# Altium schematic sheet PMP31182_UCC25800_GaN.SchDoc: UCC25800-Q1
size A2; Date: Not shown in title block; ApprovedBy: Not shown in title block; CheckedBy: Not shown in title block; Author: Not shown in title block; CompanyName: Not shown in title block; Engineer: Not shown in title block; Organization: Not shown in title block; Address1: Not shown in title block; Address2: Not shown in title block; Address3: Not shown in title block; Address4: Not shown in title block; DocumentNumber: 2; Revision: Use project parameter SCH_Rev; SheetNumber: 2; SheetTotal: 3; PageSetup: Record=PageOptions¦CenterHorizontal=True¦CenterVertical=True¦PrintScale=1.00¦XCorrection=1.00¦YCorrection=1.00¦PrintKind=0¦BorderSize=5000000¦LeftOffset=0¦BottomOffset=0¦Orientation=2¦PaperLength=1000¦PaperWidth=1000¦Scale=100¦PaperSource=15¦PrintQuality=600¦MediaType=1¦DitherType=10¦PaperKind=Letter¦PrintScaleMode=1
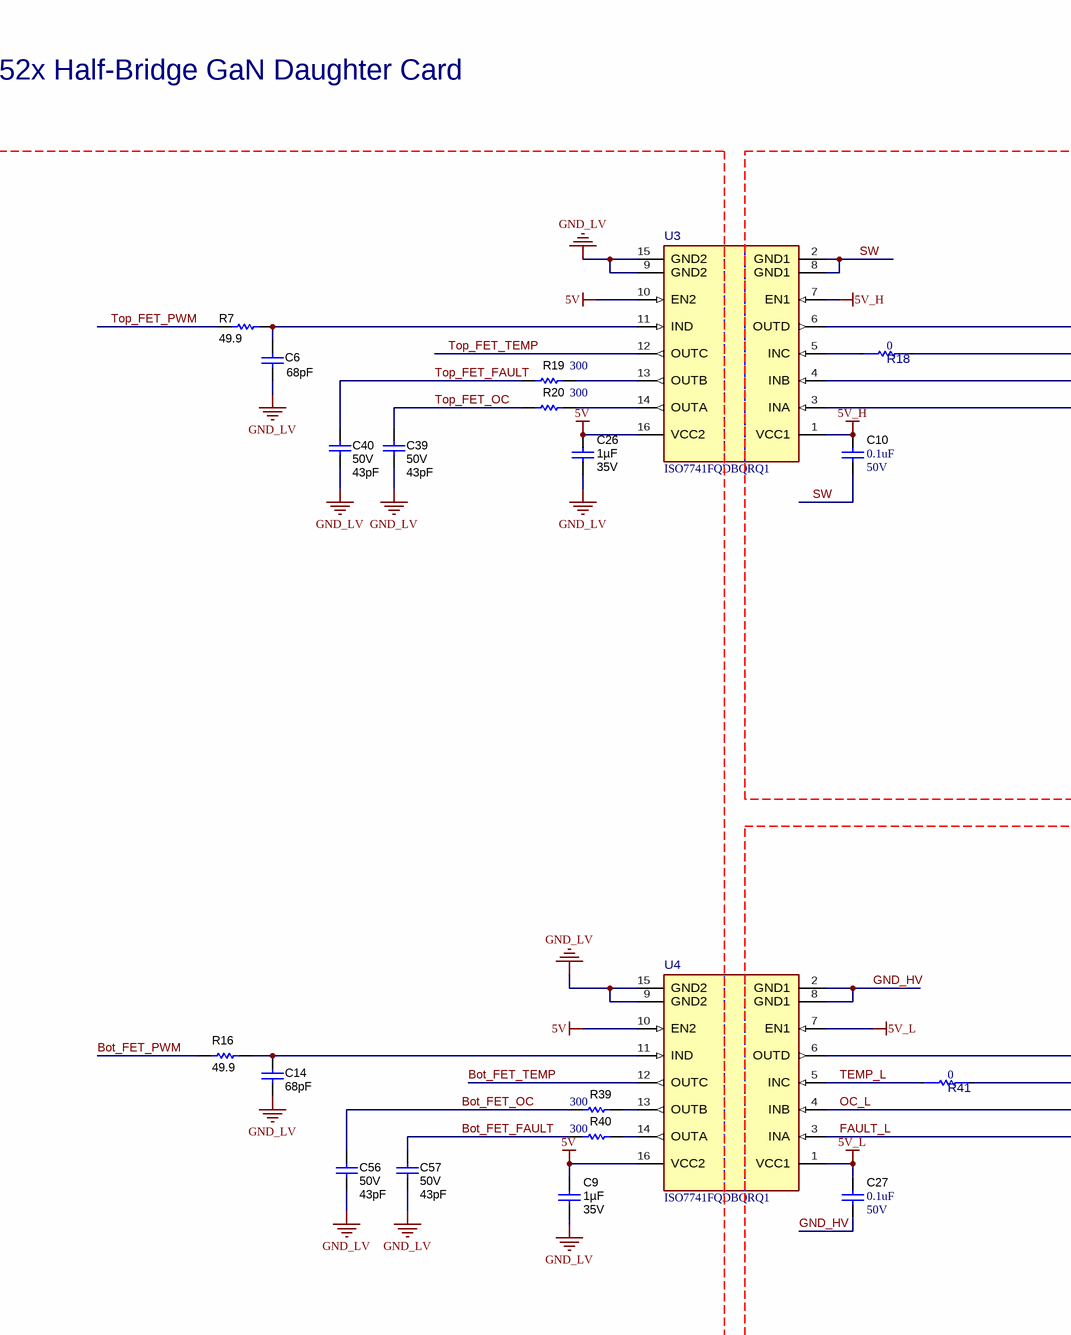
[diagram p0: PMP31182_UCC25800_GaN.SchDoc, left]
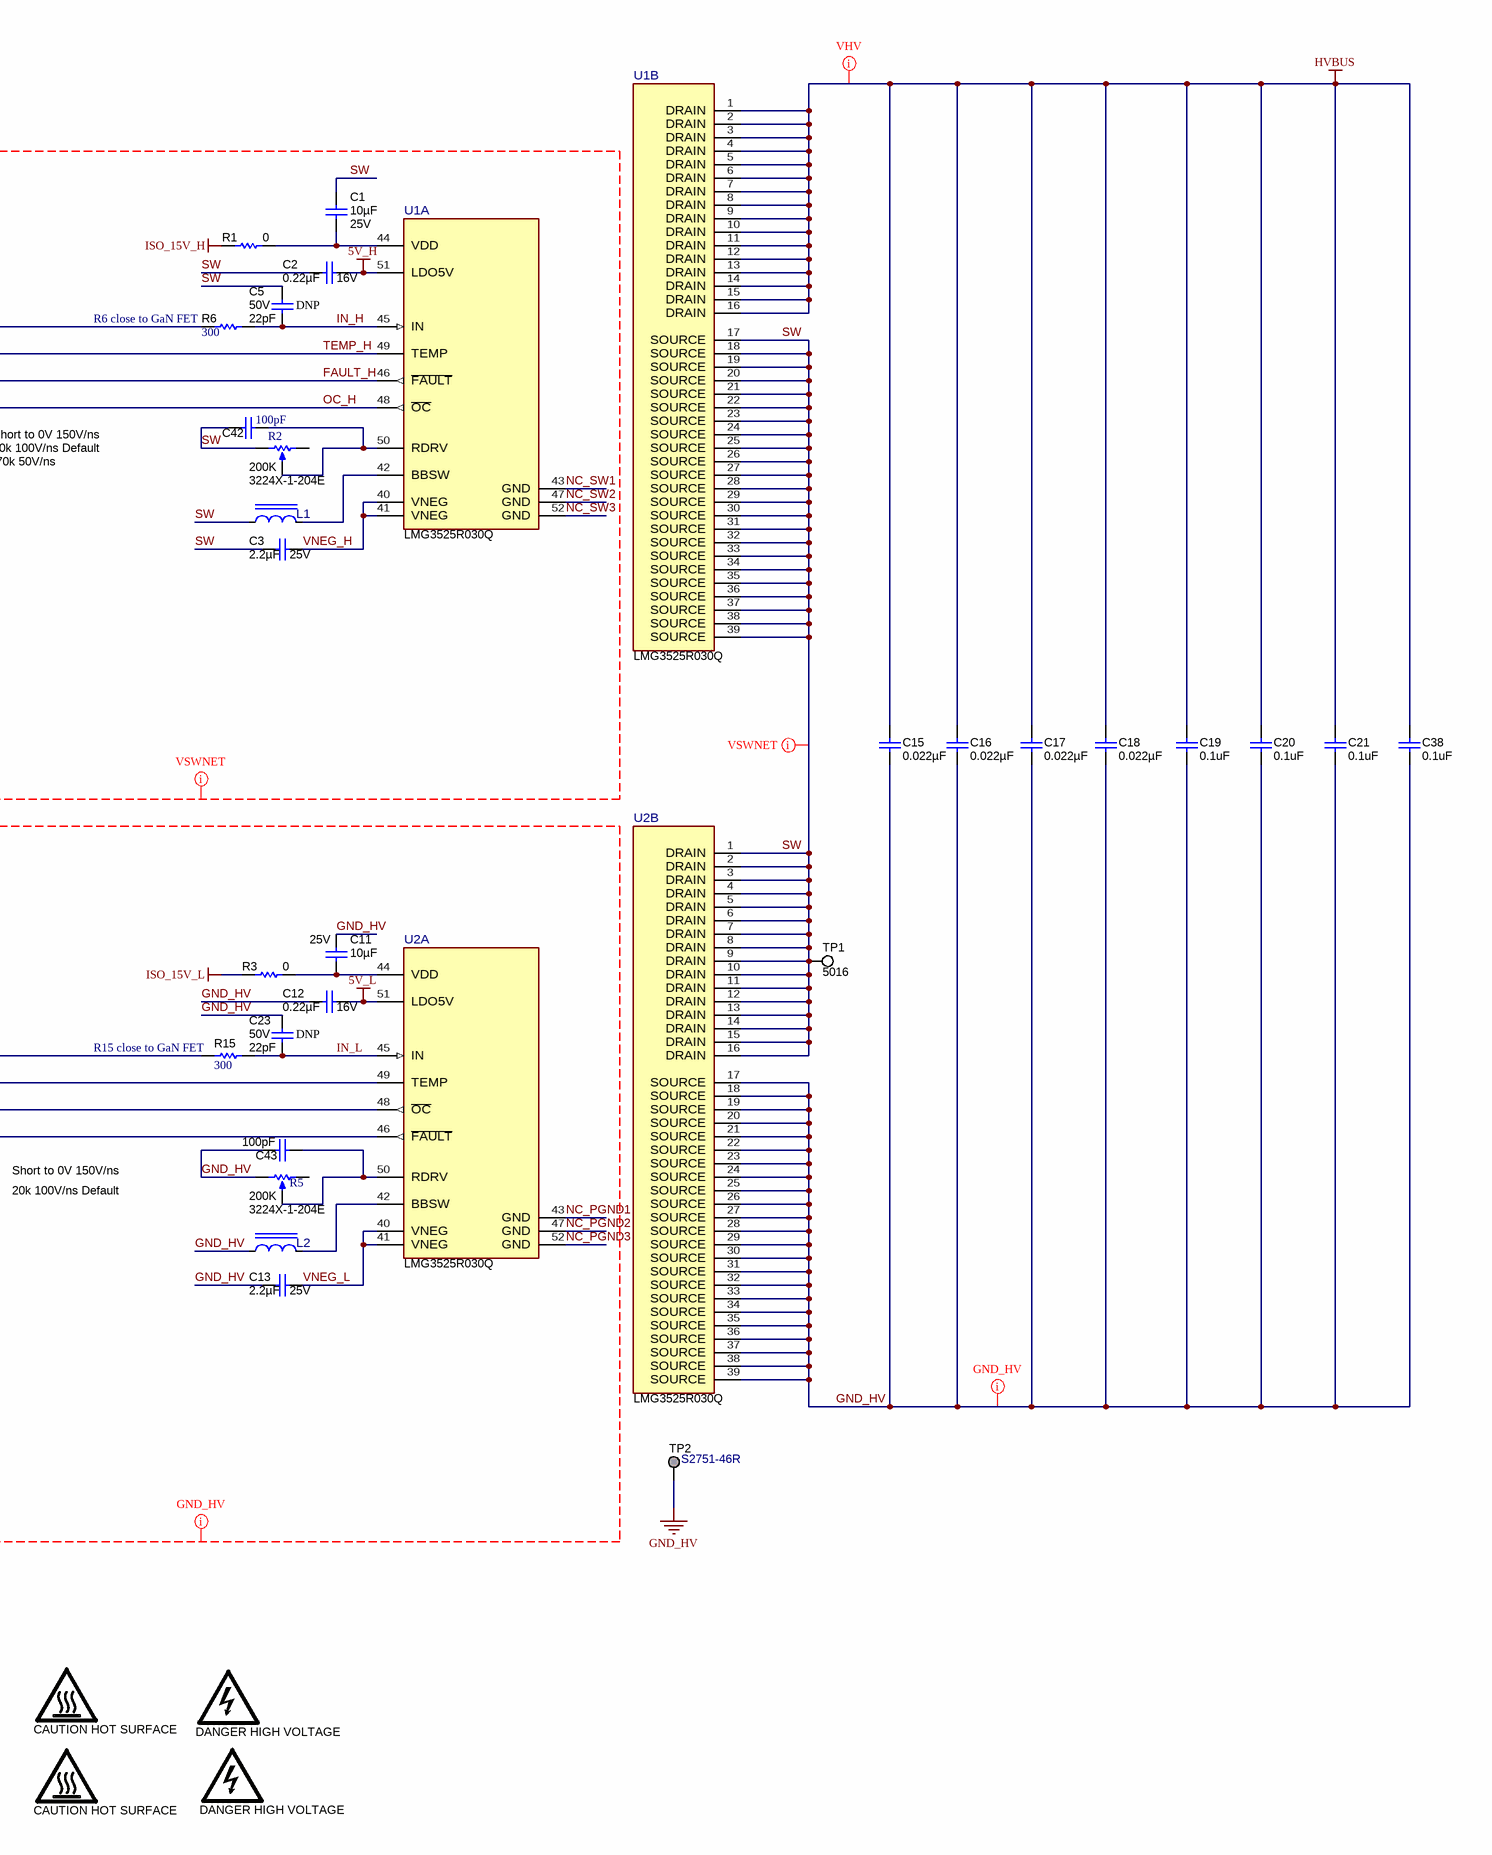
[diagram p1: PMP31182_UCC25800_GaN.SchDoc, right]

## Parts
(Parts that share a designator on the sheet are numbered #1, #2 ... from top to bottom, then left to right.)
C1  VDC_V: 25V  ValueDisplayed: 10µF  [1206_180]  (hidden comment: TMK316AB7106KLHT)
C2  VDC_V: 16V  ValueDisplayed: 0.22µF  [0402]  (hidden comment: GCM155R71C224KE02D)
C3  Cap_F: 2.2µF  VDC_V: 25V  [0805_HV]  (hidden comment: CGA4J3X7R1E225K125AB)
C5  VDC_V: 50V  ValueDisplayed: 22pF  [0402]  (hidden comment: GCM1555C1H220JA16D)
C6  ValueDisplayed: 68pF  [0402]  (hidden comment: C1005C0G1H680J050BA)
C9  VDC_V: 35V  ValueDisplayed: 1µF  [0402]  (hidden comment: GRT155R6YA105KE13D)
C10  VDC_V: 50V  ValueDisplayed: 0.1uF  [0402]  (hidden comment: GCM155R71H104KE02D)
C11  VDC_V: 25V  ValueDisplayed: 10µF  [1206_180]  (hidden comment: TMK316AB7106KLHT)
C12  VDC_V: 16V  ValueDisplayed: 0.22µF  [0402]  (hidden comment: GCM155R71C224KE02D)
C13  Cap_F: 2.2µF  VDC_V: 25V  [0805_HV]  (hidden comment: CGA4J3X7R1E225K125AB)
C14  ValueDisplayed: 68pF  [0402]  (hidden comment: C1005C0G1H680J050BA)
C15  ValueDisplayed: 0.022µF  [1206_190]  (hidden comment: C1206C223KDRACTU)
C16  ValueDisplayed: 0.022µF  [1206_190]  (hidden comment: C1206C223KDRACTU)
C17  ValueDisplayed: 0.022µF  [1206_190]  (hidden comment: C1206C223KDRACTU)
C18  ValueDisplayed: 0.022µF  [1206_190]  (hidden comment: C1206C223KDRACTU)
C19  ValueDisplayed: 0.1uF  [1812_254]  (hidden comment: C1812W104KDRACTU)
C20  ValueDisplayed: 0.1uF  [1812_254]  (hidden comment: C1812W104KDRACTU)
C21  ValueDisplayed: 0.1uF  [1812_254]  (hidden comment: C1812W104KDRACTU)
C23  VDC_V: 50V  ValueDisplayed: 22pF  [0402]  (hidden comment: GCM1555C1H220JA16D)
C26  VDC_V: 35V  ValueDisplayed: 1µF  [0402]  (hidden comment: GRT155R6YA105KE13D)
C27  VDC_V: 50V  ValueDisplayed: 0.1uF  [0402]  (hidden comment: GCM155R71H104KE02D)
C38  ValueDisplayed: 0.1uF  [1812_254]  (hidden comment: C1812W104KDRACTU)
C39  VDC_V: 50V  ValueDisplayed: 43pF  [0402]  (hidden comment: GCQ1555C1H430JB01D)
C40  VDC_V: 50V  ValueDisplayed: 43pF  [0402]  (hidden comment: GCQ1555C1H430JB01D)
C42  ValueDisplayed: 100pF  [0402]  (hidden comment: CGA2B2C0G1H101J050BA)
C43  ValueDisplayed: 100pF  [0402]  (hidden comment: CGA2B2C0G1H101J050BA)
C56  VDC_V: 50V  ValueDisplayed: 43pF  [0402]  (hidden comment: GCQ1555C1H430JB01D)
C57  VDC_V: 50V  ValueDisplayed: 43pF  [0402]  (hidden comment: GCQ1555C1H430JB01D)
L1  MPIA2510V2-4R7-R  [FP-MPIA2510V2-4R7-R_1008-MFG]  (value not drawn)
L2  MPIA2510V2-4R7-R  [FP-MPIA2510V2-4R7-R_1008-MFG]  (value not drawn)
LOGO?#1  CAUTION HOT SURFACE  [IEC_HotSurface_Small]  (no BOM)
LOGO?#2  DANGER HIGH VOLTAGE  [IEC_HighVoltage_Small]  (no BOM)
LOGO?#3  CAUTION HOT SURFACE  [IEC_HotSurface_Small]  (no BOM)
LOGO?#4  DANGER HIGH VOLTAGE  [IEC_HighVoltage_Small]  (no BOM)
R1  ValueDisplayed: 0  [0805_HV]  (hidden comment: CRCW08050000Z0EAHP)
R2  3224X-1-204E  value 200K  [TRIM_3224X]
R3  ValueDisplayed: 0  [0805_HV]  (hidden comment: CRCW08050000Z0EAHP)
R5  3224X-1-204E  value 200K  [TRIM_3224X]
R6  ValueDisplayed: 300  [0402]  (hidden comment: CRCW0402300RJNED)
R7  ValueDisplayed: 49.9  [0402]  (hidden comment: CRCW040249R9FKED)
R15  ValueDisplayed: 300  [0402]  (hidden comment: CRCW0402300RJNED)
R16  ValueDisplayed: 49.9  [0402]  (hidden comment: CRCW040249R9FKED)
R18  Res_ohm: 0  [FP-ERJ-3GEY0R00V_0603-MFG]  (hidden comment: ERJ-3GEY0R00V)
R19  ValueDisplayed: 300  [0402]  (hidden comment: CRCW0402300RJNED)
R20  ValueDisplayed: 300  [0402]  (hidden comment: CRCW0402300RJNED)
R39  ValueDisplayed: 300  [0402]  (hidden comment: CRCW0402300RJNED)
R40  ValueDisplayed: 300  [0402]  (hidden comment: CRCW0402300RJNED)
R41  Res_ohm: 0  [FP-ERJ-3GEY0R00V_0603-MFG]  (hidden comment: ERJ-3GEY0R00V)
TP1  5016  [Testpoint_Keystone_Compact]
TP2  S2751-46R  [Harwin_S2751-46R]
U1  LMG3525R030Q  [RQS0052A-MFG]  (parts A,B of 2)
U2  LMG3525R030Q  [RQS0052A-MFG]  (parts A,B of 2)
U3  ISO7741FQDBQRQ1  [DBQ0016A-MFG]
U4  ISO7741FQDBQRQ1  [DBQ0016A-MFG]

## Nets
5V: C9.1 C26.1 U3.10(EN2) U3.16(VCC2) U4.10(EN2) U4.16(VCC2)
5V_H: C2.1 C10.1 U1.51(LDO5V) U3.1(VCC1) U3.7(EN1)
5V_L: C12.1 C27.1 U2.51(LDO5V) U4.1(VCC1) U4.7(EN1)
GND_HV: C11.1 C12.2 C13.1 C15.2 C16.2 C17.2 C18.2 C19.2 C20.2 C21.2 C23.1 C27.2 C38.2 C43.1 L2.1 R5.1(CCW) TP2.1 U2.17(SOURCE) U2.18(SOURCE) U2.19(SOURCE) U2.20(SOURCE) U2.21(SOURCE) U2.22(SOURCE) U2.23(SOURCE) U2.24(SOURCE) U2.25(SOURCE) U2.26(SOURCE) U2.27(SOURCE) U2.28(SOURCE) U2.29(SOURCE) U2.30(SOURCE) U2.31(SOURCE) U2.32(SOURCE) U2.33(SOURCE) U2.34(SOURCE) U2.35(SOURCE) U2.36(SOURCE) U2.37(SOURCE) U2.38(SOURCE) U2.39(SOURCE) U4.2(GND1) U4.8(GND1)
GND_LV: C6.2 C9.2 C14.1 C26.2 C39.2 C40.2 C56.2 C57.2 U3.9(GND2) U3.15(GND2) U4.9(GND2) U4.15(GND2)
HVBUS: C15.1 C16.1 C17.1 C18.1 C19.1 C20.1 C21.1 C38.1 U1.1(DRAIN) U1.2(DRAIN) U1.3(DRAIN) U1.4(DRAIN) U1.5(DRAIN) U1.6(DRAIN) U1.7(DRAIN) U1.8(DRAIN) U1.9(DRAIN) U1.10(DRAIN) U1.11(DRAIN) U1.12(DRAIN) U1.13(DRAIN) U1.14(DRAIN) U1.15(DRAIN) U1.16(DRAIN)
ISO_15V_H: R1.1
ISO_15V_L: R3.1
Bot_FET_FAULT: C57.1 R40.2
Bot_FET_OC: C56.1 R39.2
Bot_FET_PWM: R16.1
Bot_FET_TEMP: U4.12(OUTC)
FAULT_H: U1.46(~{FAULT}) U3.4(INB)
FAULT_L: U2.46(~{FAULT}) U4.3(INA)
IN_H: C5.2 R6.2 U1.45(IN)
IN_L: C23.2 R15.2 U2.45(IN)
NC_PGND1: U2.43(GND)
NC_PGND2: U2.47(GND)
NC_PGND3: U2.52(GND)
NC_SW1: U1.43(GND)
NC_SW2: U1.47(GND)
NC_SW3: U1.52(GND)
OC_H: U1.48(~{OC}) U3.3(INA)
OC_L: U2.48(~{OC}) U4.4(INB)
SW: C1.2 C2.2 C3.1 C5.1 C10.2 C42.2 L1.1 R2.1(CCW) TP1.1 U1.17(SOURCE) U1.18(SOURCE) U1.19(SOURCE) U1.20(SOURCE) U1.21(SOURCE) U1.22(SOURCE) U1.23(SOURCE) U1.24(SOURCE) U1.25(SOURCE) U1.26(SOURCE) U1.27(SOURCE) U1.28(SOURCE) U1.29(SOURCE) U1.30(SOURCE) U1.31(SOURCE) U1.32(SOURCE) U1.33(SOURCE) U1.34(SOURCE) U1.35(SOURCE) U1.36(SOURCE) U1.37(SOURCE) U1.38(SOURCE) U1.39(SOURCE) U2.1(DRAIN) U2.2(DRAIN) U2.3(DRAIN) U2.4(DRAIN) U2.5(DRAIN) U2.6(DRAIN) U2.7(DRAIN) U2.8(DRAIN) U2.9(DRAIN) U2.10(DRAIN) U2.11(DRAIN) U2.12(DRAIN) U2.13(DRAIN) U2.14(DRAIN) U2.15(DRAIN) U2.16(DRAIN) U3.2(GND1) U3.8(GND1)
TEMP_H: R18.2 U1.49(TEMP)
TEMP_L: R41.1 U4.5(INC)
Top_FET_FAULT: C40.1 R19.2
Top_FET_OC: C39.1 R20.2
Top_FET_PWM: R7.1
Top_FET_TEMP: U3.12(OUTC)
VNEG_H: C3.2 U1.40(VNEG) U1.41(VNEG)
VNEG_L: C13.2 U2.40(VNEG) U2.41(VNEG)
NetC1_1: C1.1 R1.2 U1.44(VDD)
NetC6_1: C6.1 R7.2 U3.11(IND)
NetC11_2: C11.2 R3.2 U2.44(VDD)
NetC14_2: C14.2 R16.2 U4.11(IND)
NetC42_1: C42.1 R2.2(WIPER) U1.50(RDRV)
NetC43_2: C43.2 R5.2(WIPER) U2.50(RDRV)
NetL1_2: L1.2 U1.42(BBSW)
NetL2_2: L2.2 U2.42(BBSW)
NetR6_1: R6.1 U3.6(OUTD)
NetR15_1: R15.1 U4.6(OUTD)
NetR18_1: R18.1 U3.5(INC)
NetR19_1: R19.1 U3.13(OUTB)
NetR20_1: R20.1 U3.14(OUTA)
NetR39_1: R39.1 U4.13(OUTB)
NetR40_1: R40.1 U4.14(OUTA)
NetR41_2: R41.2 U2.49(TEMP)

Not connected (* = marked no-connect by the designer): R2 3(CW); R5 3(CW)

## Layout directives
net class VSWNET: 5V_H, FAULT_H, IN_H, ISO_15V_H, NC_SW1, NC_SW2, NC_SW3, OC_H, SW, TEMP_H, VNEG_H
net class VHV: HVBUS
net class INGND: (no net found under the mark)
net class PGND: 5V_L, FAULT_L, GND_HV, IN_L, ISO_15V_L, NC_PGND1, NC_PGND2, NC_PGND3, OC_L, TEMP_L, VNEG_L

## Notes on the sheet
- LMG352x Half-Bridge GaN Daughter Card
- (near C5) DNP
- (near R6) R6 close to GaN FET
- Short to 0V 150V/ns
- 20k 100V/ns Default
- 70k 50V/ns
- (near R15) R15 close to GaN FET
- (near C23) DNP

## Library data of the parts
C1 C11 = CMP-0750154-1: CAP, CERM, 10 µF, 25 V,+/- 10%, X7R, AEC-Q200 Grade 1, 1206; Manufacturer: Taiyo Yuden; AEC Qualified: Y; SizeZ_mm: 1.8; TaMax_C: 125°C; TaMin_C: -55°C; Cap_Case: 1206; Polarized: N; AEC Grade: 1; SizeY_mm: 1.6; Value: 10uF; SizeX_mm: 3.2; SizeAreaWB_mm2: 10.92; AEC Category: Q200; U/M: EA; SizeArea_mm2: 5.12
C2 C12 = CMP-0078265-1: CAP, CERM, 0.22 µF, 16 V,+/- 10%, X7R, AEC-Q200 Grade 1, 0402; Manufacturer: MuRata; TaMin_C: -55°C; Polarized: N; SizeAreaWB_mm2: 3; U/M: EA; Value: 0.22uF; TaMax_C: 125°C; SizeZ_mm: 0.6; SizeX_mm: 1; SizeY_mm: 0.5; AEC Qualified: Y; Cap_F: 220nF; AEC Category: Q200
C3 C13 = CMP-0007975-2: CAP, CERM, 2.2 uF, 25 V, +/- 10%, X7R, AEC-Q200 Grade 1, 0805; Manufacturer: TDK; TaMin_C: -55°C; Polarized: N; SizeAreaWB_mm2: 6.75; Value1: Unknown; U/M: EA; Value: 2.2uF; TaMax_C: 125°C; SizeZ_mm: 1.45; SizeX_mm: 2; SizeY_mm: 1.25; Cap_Case: 0805; SizeArea_mm2: 2.5; AEC Qualified: Y; AEC Grade: 1; AEC Category: Q200
C5 C23 = CMP-0006348-2: CAP, CERM, 22 pF, 50 V, +/- 5%, C0G/NP0, AEC-Q200 Grade 1, 0402; Manufacturer: MuRata; TaMin_C: -55°C; Polarized: N; SizeAreaWB_mm2: 3; Value1: Unknown; U/M: EA; Value: 22pF; TaMax_C: 125°C; SizeZ_mm: 0.6; SizeX_mm: 1; SizeY_mm: 0.5; AEC Qualified: Y; AEC Category: Q200
C6 C14 = CMP-0006251-2: CAP, CERM, 68 pF, 50 V, +/- 5%, C0G/NP0, 0402; Manufacturer: TDK; Alternate Manufacturer: Murata; Alternate PartNumber: GRM1555C1H680JA01D; TaMin_C: -55°C; Polarized: N; SizeAreaWB_mm2: 3; Value1: Unknown; U/M: EA; Value: 68pF; TaMax_C: 125°C; SizeZ_mm: 0.6; SizeX_mm: 1; SizeY_mm: 0.5; Value2: 50V; AEC Category: Q200
C9 C26 = CMP-0750099-1: CAP, CERM, 1 µF, 35 V,+/- 10%, X5R, AEC-Q200 Grade 3, 0402; Manufacturer: MuRata; AEC Grade: 3; AEC Category: Q200; Value: 1uF; SizeArea_mm2: 0.5; SizeZ_mm: 0.6; AEC Qualified: Y; TaMin_C: -55°C; SizeX_mm: 1; U/M: EA; Polarized: N; TaMax_C: 85°C
C10 C27 = CMP-0006356-2: CAP, CERM, 0.1 uF, 50 V, +/- 10%, X7R, AEC-Q200 Grade 1, 0402; Manufacturer: MuRata; TaMin_C: -55°C; Polarized: N; SizeAreaWB_mm2: 3; Value1: Unknown; U/M: EA; Value: 0.1uF; TaMax_C: 125°C; SizeZ_mm: 0.6; SizeX_mm: 1; SizeY_mm: 0.5; AEC Qualified: Y; Cap_F: 100nF; AEC Category: Q200
C15-C18 = CMP-0084048-1: CAP, CERM, 0.022 µF, 1000 V,+/- 10%, X7R, AEC-Q200 Grade 1, 1206; Manufacturer: Kemet; Polarized: N; CompType: Capacitor; Value: 0.022uF; U/M: EA; Cap_F: 22nF; VDC_V: 1kV; Value2: 1000V; TaMin_C: -55°C; TaMax_C: 125°C; Cap_Case: 1206; SizeArea_mm2: 5.12; SizeAreaWB_mm2: 10.92; SizeX_mm: 3.2; SizeY_mm: 1.6; SizeZ_mm: 1.9; AEC Category: Q200; AEC Qualified: Y; AEC Grade: 1
C19-C21 C38 = CMP-0009326-2: CAP, CERM, 0.1 uF, 1000 V, +/- 10%, X7R, 1812; Manufacturer: Kemet; Polarized: N; Value: 0.1uF; U/M: EA; Cap_F: 100nF; Value1: Unknown; VDC_V: 1kV; Value2: 1000V; TaMin_C: -55°C; TaMax_C: 125°C; Cap_Case: 1812; AEC Category: Q200; SizeArea_mm2: 14.4; SizeAreaWB_mm2: 23.1; SizeX_mm: 4.5; SizeY_mm: 3.2; SizeZ_mm: 2.54
C39 C40 C56 C57 = CMP-0860835-1: CAP, CERM, 43 pF, 50 V,+/- 5%, C0G/NP0, AEC-Q200 Grade 1, 0402; Manufacturer: MuRata; SizeY_mm: 0.5; SizeZ_mm: 0.6; AEC Qualified: Y; AEC Grade: 1; AEC Category: Q200; U/M: EA; Value: 43pF; Polarized: N; TaMin_C: -55°C; SizeAreaWB_mm2: 3; TaMax_C: 125°C
C42 = CMP-0006308-2: CAP, CERM, 100 pF, 50 V, +/- 5%, C0G/NP0, AEC-Q200 Grade 1, 0402; Manufacturer: TDK; TaMin_C: -55°C; Polarized: N; SizeAreaWB_mm2: 3; Value1: Unknown; U/M: EA; Value: 100pF; TaMax_C: 125°C; SizeZ_mm: 0.6; SizeX_mm: 1; SizeY_mm: 0.5; Value2: 50V; AEC Qualified: Y; AEC Category: Q200
C43 = CMP-0006308-1: CAP, CERM, 100 pF, 50 V, +/- 5%, C0G/NP0, AEC-Q200 Grade 1, 0402; Manufacturer: TDK; TaMin_C: -55°C; Polarized: N; SizeAreaWB_mm2: 3; Value1: Unknown; U/M: EA; Value: 100pF; TaMax_C: 125°C; SizeZ_mm: 0.6; SizeX_mm: 1; SizeY_mm: 0.5; Value2: 50V; AEC Qualified: Y; AEC Category: Q200
L1 L2 = CMP-0090507-1: 4.7µH Shielded Molded Inductor 1.22A 262mOhm Max 1008 (2520 Metric); Manufacturer: Eaton; Material: Metal Composite; Value: 4.7uH; Test Frequency: 1MHz; Isat: 1.8A; DCR_ohm: 0.262; AEC Grade: Grade 1; Tolerance_%: 20%; AEC Qualified: Yes; Self Resonant Frequency: 25MHz; SizeZ_mm: 1.05mm; Shrouded: true
LOGO?#1 LOGO?#3 = CMP-0074837-1: IEC 61010-1 Hot Surface Warning; SymbolCreator: a0412235; Lib Reference: IEC_HotSurface
LOGO?#2 LOGO?#4 = CMP-0074835-1: IEC 61010-1 High Voltage Warning; SymbolCreator: a0412235; Lib Reference: IEC_HighVoltage
R1 R3 = CMP-0020443-3: RES, 0, 5%, 0.333 W, AEC-Q200 Grade 0, 0805; Manufacturer: Vishay-Dale; Power_W: 333mW; TempCo: 200 ppm/C; Value_Code: 0000; Value: 0; EIA_Code: E24; SizeX_mm: 2; SizeY_mm: 1.25; SizeZ_mm: 1.45; Value2: 0.333W; SizeArea_mm2: 2.5; AEC Qualified: Y; AEC Category: Q200; VDC_V: 150V
R2 R5 = CMP-0002064-2: Trimmer, 200 K, 0.25 W, SMD; Manufacturer: Bourns
R6 R15 R19 R20 R39 R40 = CMP-0026902-3: RES, 300, 5%, 0.063 W, AEC-Q200 Grade 0, 0402; Manufacturer: Vishay-Dale; Power_W: 63mW; TempCo: 200 ppm/C; Value_Code: 300R; Value: 300; EIA_Code: E24; SizeX_mm: 1; SizeY_mm: 0.5; SizeZ_mm: 0.6; Value2: 0.063W; AEC Qualified: Y; VDC_V: 50V; AEC Category: Q200; AEC Grade: 0
R7 R16 = CMP-0026404-2: RES, 49.9, 1%, 0.063 W, AEC-Q200 Grade 0, 0402; Manufacturer: Vishay-Dale; Power_W: 63mW; TempCo: 100 ppm/C; Value_Code: 49R9; Value: 49.9; EIA_Code: E96; SizeX_mm: 1; SizeY_mm: 0.5; SizeZ_mm: 0.6; Value2: 0.063W; AEC Qualified: Y; VDC_V: 50V; AEC Category: Q200; AEC Grade: 0
R18 R41 = CMP-0089143-1: 0 Ohms Jumper 0.1W, 1/10W Chip Resistor 0603 (1608 Metric) Automotive AEC-Q200 Thick Film; Manufacturer: Panasonic; SizeZ_mm: 0.55mm; AEC Grade: Grade 0; VDC_V: 75V; TempCo: -100/+600ppm/°C; AEC Qualified: Yes; Power_W: 100mW; Tolerance_%: 5%
TP1 = CMP-0055153-1: Test Point, Compact, SMT; Manufacturer: Keystone; CNHeader: FALSE; Green_Lifecycle: Active; Green_REACh: Passed; CT: TRUE
TP2 = CMP-0003968-1: Test Point, SMT; Manufacturer: Harwin
U1 U2 = CMP-0089968-1: 650-V 30-mΩ GaN FET with Integrated Driver and Protection; Manufacturer: Texas Instruments; Output Voltage: 520V; Nominal Supply Current: 540uA; Min Supply Voltage: 7.5V; Standoff Height: 0mm; AEC Grade: Grade 1; Max Supply Voltage: 18V; Number Of Outputs: 1; AEC Qualified: Yes; TJmax_C: +125°C; SizeZ_mm: 1mm
U3 U4 = CMP-0090469-1: General Purpose Digital Isolator 2500Vrms 4 Channel 100Mbps 85kV/µs CMTI 16-SSOP (0.154", 3.90mm Width); Manufacturer: Texas Instruments; TaMin_C: -40°C; TaMax_C: +125°C; TJmax_C: +150°C; AEC Grade: Grade 1; Min Supply Voltage: 2.25V; AEC Qualified: Yes; Max Supply Voltage: 5.5V; Standoff Height: 0.11mm; Nominal Supply Current: 1.5-18mA; SizeZ_mm: 1.75mm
